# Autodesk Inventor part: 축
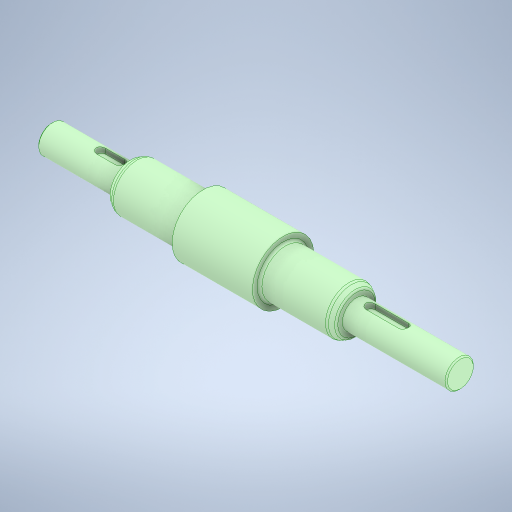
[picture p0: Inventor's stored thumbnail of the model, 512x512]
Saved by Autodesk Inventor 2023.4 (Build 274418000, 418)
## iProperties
Created: 2024-04
Part Number: 축
Material: 강철, 탄소
Document SubType Name: Modeling
Designer: Edu03
Density: 7.85 g/cm^3
Appearance: 기본값
Author: jhkim
Sending System: Autodesk Inventor 2025
Preprocessor: ST-DEVELOPER v20
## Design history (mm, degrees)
feature "솔리드1"
node "솔리드2"
